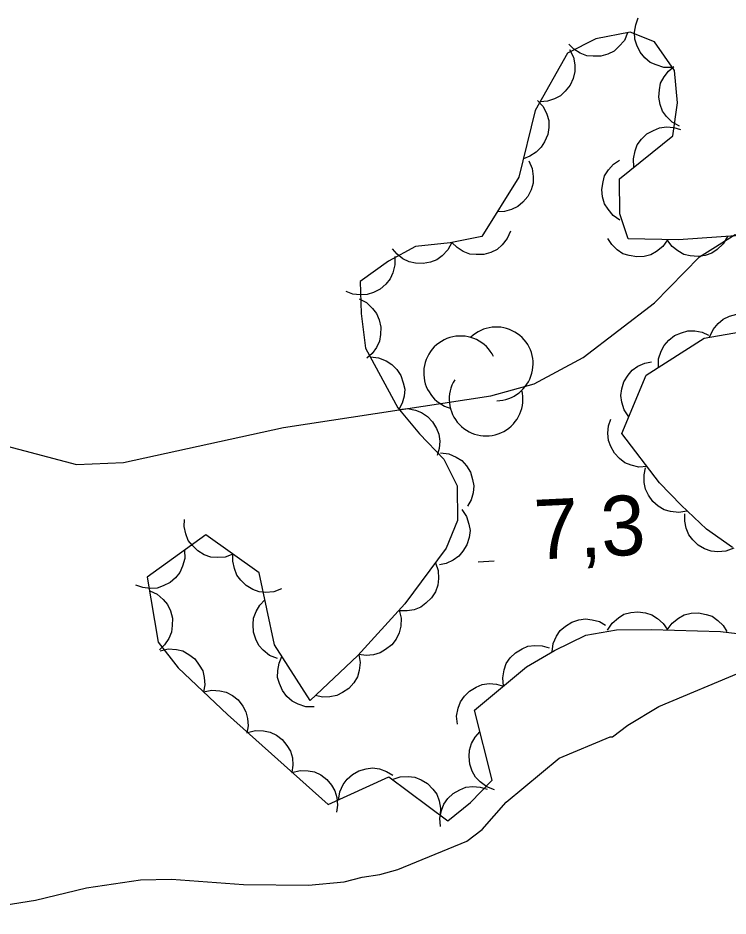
# Model space of a CAD drawing. Extents: x 336540 to 340074, y 5572036 to 5573747.
# Drawn here: x 337087.41 to 337123.07, y 5573176.22 to 5573221.28 of the extents above; entities that cross this region are included whole.
import ezdxf

# ---------------------------------------------------------------- set-up
doc = ezdxf.new("R2010")
doc.units = 0
for name, color, linetype in [('Niveau 2', 7, 'Continuous'), ('Niveau 3', 7, 'Continuous'), ('Niveau 44', 7, 'Continuous')]:
    doc.layers.add(name, color=color, linetype=linetype)

msp = doc.modelspace()

# ---------------------------------------------------------------- linework, layer by layer
at = {"layer": 'Niveau 2'}
for points in [[(337082.81, 5573200.86), (337090.35, 5573198.87), (337092.72, 5573198.98), (337100.75, 5573200.74), (337111.16, 5573202.32), (337113.33, 5573202.93), (337115.79, 5573204.25), (337119.38, 5573206.98), (337121.63, 5573209.29), (337123.43, 5573210.41), (337126.65, 5573210.23), (337131.4, 5573210.47), (337137.08, 5573211.79), (337144.21, 5573214.53), (337147.21, 5573215.37), (337153.27, 5573216.18), (337159.76, 5573218.05)], [(337117.14, 5573185.21), (337117.26, 5573185.21), (337118.03, 5573185.79), (337119.59, 5573186.73), (337123.82, 5573188.51)], [(337083.24, 5573176.22), (337088.29, 5573177.01), (337090.86, 5573177.63), (337093.56, 5573178.03), (337095.13, 5573178.07), (337098.74, 5573177.81), (337102, 5573177.77), (337103.8, 5573177.93), (337104.7, 5573178.17), (337105.59, 5573178.3), (337106.49, 5573178.55), (337109.95, 5573179.98), (337110.72, 5573180.56), (337111.93, 5573181.94), (337114.58, 5573184.14), (337117.14, 5573185.21)]]:
    msp.add_lwpolyline(points, dxfattribs=at)
at = {"layer": 'Niveau 3'}
msp.add_line((337110.52, 5573194), (337111.32, 5573194.04), dxfattribs=at)
at = {"layer": 'Niveau 44'}
for points in [[(337120.26, 5573218.8), (337119.84, 5573218.8), (337119.45, 5573218.92), (337119.15, 5573219.05), (337118.88, 5573219.28), (337118.65, 5573219.57), (337118.48, 5573219.91), (337118.38, 5573220.22), (337118.37, 5573220.57), (337118.43, 5573220.94), (337118.56, 5573221.28)], [(337123.68, 5573210.36), (337120.58, 5573210.14), (337118.05, 5573210.19), (337117.64, 5573211.46), (337117.62, 5573213.21), (337120.29, 5573215.36), (337120.52, 5573217.03), (337120.37, 5573218.64), (337119.38, 5573220.08), (337118.15, 5573220.56), (337116.43, 5573220.23), (337115.01, 5573219.51), (337113.38, 5573216.63), (337112.56, 5573213.3), (337110.7, 5573210.31), (337109.12, 5573210), (337107.37, 5573209.82), (337106.01, 5573209.08), (337104.6, 5573208.06), (337104.64, 5573206.45), (337104.86, 5573204.72), (337106.49, 5573201.72), (337107.57, 5573200.41), (337108.79, 5573199.15), (337109.47, 5573197.81), (337109.48, 5573196.07), (337108.91, 5573194.67), (337106.84, 5573191.88), (337104.48, 5573189.3), (337102.08, 5573187.03), (337100.29, 5573189.83), (337099.52, 5573193.44), (337096.85, 5573195.35), (337093.91, 5573193.23), (337094.46, 5573189.96), (337095.45, 5573188.68), (337097.93, 5573186.33), (337102.99, 5573181.81), (337106.03, 5573183.2), (337108.99, 5573181), (337110.14, 5573181.92), (337111.22, 5573183.04), (337110.34, 5573186.55), (337112.95, 5573188.73), (337114.36, 5573189.54), (337115.93, 5573190.32), (337117.47, 5573190.58), (337119.22, 5573190.6), (337122.69, 5573190.5), (337124.36, 5573190.3)], [(337118.02, 5573220.54), (337117.86, 5573220.15), (337117.59, 5573219.84), (337117.35, 5573219.62), (337117.03, 5573219.47), (337116.68, 5573219.36), (337116.29, 5573219.36), (337115.97, 5573219.38), (337115.64, 5573219.52), (337115.33, 5573219.72), (337115.07, 5573219.97)], [(337115.11, 5573219.69), (337115.3, 5573219.32), (337115.37, 5573218.92), (337115.38, 5573218.59), (337115.29, 5573218.25), (337115.14, 5573217.91), (337114.89, 5573217.61), (337114.66, 5573217.38), (337114.35, 5573217.22), (337114, 5573217.11), (337113.64, 5573217.08)], [(337120.63, 5573215.85), (337120.26, 5573216.05), (337119.98, 5573216.34), (337119.78, 5573216.61), (337119.66, 5573216.94), (337119.59, 5573217.3), (337119.62, 5573217.68), (337119.68, 5573218.01), (337119.85, 5573218.32), (337120.07, 5573218.61), (337120.35, 5573218.84)], [(337113.5, 5573217.14), (337113.78, 5573216.83), (337113.96, 5573216.46), (337114.06, 5573216.14), (337114.06, 5573215.79), (337114.01, 5573215.43), (337113.85, 5573215.07), (337113.69, 5573214.79), (337113.43, 5573214.55), (337113.12, 5573214.35), (337112.79, 5573214.22)], [(337118.34, 5573213.79), (337118.31, 5573214.21), (337118.4, 5573214.61), (337118.51, 5573214.92), (337118.72, 5573215.2), (337118.98, 5573215.46), (337119.32, 5573215.64), (337119.62, 5573215.77), (337119.97, 5573215.81), (337120.34, 5573215.78), (337120.68, 5573215.68)], [(337113.06, 5573214.11), (337113.23, 5573213.73), (337113.28, 5573213.32), (337113.28, 5573212.99), (337113.18, 5573212.66), (337113.01, 5573212.33), (337112.76, 5573212.04), (337112.51, 5573211.82), (337112.19, 5573211.67), (337111.84, 5573211.57), (337111.48, 5573211.56)], [(337117.64, 5573211.14), (337117.29, 5573211.37), (337117.04, 5573211.68), (337116.86, 5573211.96), (337116.77, 5573212.3), (337116.73, 5573212.67), (337116.79, 5573213.05), (337116.87, 5573213.36), (337117.06, 5573213.66), (337117.31, 5573213.94), (337117.61, 5573214.14)], [(337112.14, 5573210.59), (337111.98, 5573210.21), (337111.72, 5573209.9), (337111.48, 5573209.67), (337111.16, 5573209.52), (337110.81, 5573209.42), (337110.42, 5573209.41), (337110.1, 5573209.43), (337109.77, 5573209.57), (337109.46, 5573209.76), (337109.2, 5573210.02)], [(337120.03, 5573210.15), (337119.79, 5573209.81), (337119.47, 5573209.56), (337119.19, 5573209.39), (337118.85, 5573209.31), (337118.48, 5573209.29), (337118.1, 5573209.36), (337117.79, 5573209.45), (337117.5, 5573209.65), (337117.23, 5573209.91), (337117.03, 5573210.21)], [(337123.03, 5573210.31), (337122.82, 5573209.95), (337122.52, 5573209.67), (337122.25, 5573209.48), (337121.92, 5573209.37), (337121.56, 5573209.31), (337121.17, 5573209.35), (337120.85, 5573209.41), (337120.55, 5573209.59), (337120.26, 5573209.82), (337120.04, 5573210.1)], [(337109.2, 5573210.01), (337109, 5573209.64), (337108.72, 5573209.35), (337108.45, 5573209.15), (337108.12, 5573209.03), (337107.76, 5573208.96), (337107.38, 5573208.98), (337107.06, 5573209.04), (337106.74, 5573209.2), (337106.45, 5573209.43), (337106.22, 5573209.7)], [(337106.33, 5573209.31), (337106.34, 5573208.89), (337106.23, 5573208.5), (337106.1, 5573208.19), (337105.88, 5573207.92), (337105.6, 5573207.68), (337105.26, 5573207.51), (337104.95, 5573207.4), (337104.6, 5573207.38), (337104.23, 5573207.43), (337103.89, 5573207.55)], [(337104.55, 5573207.18), (337104.92, 5573207), (337105.21, 5573206.71), (337105.42, 5573206.46), (337105.55, 5573206.13), (337105.63, 5573205.77), (337105.61, 5573205.39), (337105.57, 5573205.06), (337105.41, 5573204.75), (337105.2, 5573204.45), (337104.93, 5573204.21)], [(337122.13, 5573205.27), (337122.31, 5573205.65), (337122.57, 5573205.95), (337122.82, 5573206.17), (337123.14, 5573206.32), (337123.5, 5573206.41), (337123.88, 5573206.41), (337124.21, 5573206.38), (337124.53, 5573206.24), (337124.84, 5573206.03), (337125.09, 5573205.77)], [(337123.29, 5573194.71), (337121.99, 5573195.63), (337120.71, 5573196.83), (337119.63, 5573197.96), (337117.73, 5573200.43), (337118.95, 5573203.36), (337121.86, 5573205.22), (337125.13, 5573205.78)], [(337119.57, 5573203.75), (337119.58, 5573204.17), (337119.7, 5573204.56), (337119.85, 5573204.85), (337120.09, 5573205.11), (337120.38, 5573205.34), (337120.73, 5573205.49), (337121.05, 5573205.58), (337121.4, 5573205.58), (337121.76, 5573205.51), (337122.09, 5573205.37)], [(337105.11, 5573204.27), (337105.52, 5573204.23), (337105.9, 5573204.07), (337106.18, 5573203.9), (337106.43, 5573203.65), (337106.63, 5573203.34), (337106.75, 5573202.98), (337106.83, 5573202.66), (337106.8, 5573202.31), (337106.7, 5573201.95), (337106.54, 5573201.63)], [(337118.08, 5573201.26), (337117.85, 5573201.61), (337117.73, 5573202), (337117.68, 5573202.33), (337117.73, 5573202.68), (337117.84, 5573203.03), (337118.05, 5573203.36), (337118.25, 5573203.61), (337118.54, 5573203.81), (337118.88, 5573203.96), (337119.23, 5573204.03)], [(337106.55, 5573201.64), (337106.97, 5573201.68), (337107.37, 5573201.6), (337107.68, 5573201.49), (337107.97, 5573201.29), (337108.23, 5573201.02), (337108.42, 5573200.69), (337108.55, 5573200.39), (337108.59, 5573200.04), (337108.56, 5573199.67), (337108.46, 5573199.33)], [(337119.01, 5573198.77), (337118.59, 5573198.74), (337118.2, 5573198.84), (337117.89, 5573198.96), (337117.61, 5573199.17), (337117.36, 5573199.44), (337117.18, 5573199.78), (337117.06, 5573200.08), (337117.03, 5573200.44), (337117.07, 5573200.81), (337117.18, 5573201.15)], [(337108.63, 5573199.46), (337109.05, 5573199.41), (337109.42, 5573199.24), (337109.7, 5573199.07), (337109.93, 5573198.81), (337110.13, 5573198.49), (337110.24, 5573198.13), (337110.31, 5573197.81), (337110.27, 5573197.46), (337110.16, 5573197.1), (337109.99, 5573196.79)], [(337121, 5573196.53), (337120.59, 5573196.46), (337120.18, 5573196.51), (337119.86, 5573196.6), (337119.56, 5573196.78), (337119.29, 5573197.02), (337119.07, 5573197.34), (337118.92, 5573197.63), (337118.85, 5573197.98), (337118.85, 5573198.35), (337118.92, 5573198.7)], [(337109.7, 5573196.62), (337109.94, 5573196.27), (337110.05, 5573195.88), (337110.11, 5573195.56), (337110.06, 5573195.21), (337109.95, 5573194.85), (337109.75, 5573194.53), (337109.55, 5573194.27), (337109.26, 5573194.07), (337108.92, 5573193.91), (337108.57, 5573193.84)], [(337098.21, 5573194.38), (337097.82, 5573194.23), (337097.41, 5573194.21), (337097.09, 5573194.23), (337096.76, 5573194.35), (337096.44, 5573194.54), (337096.17, 5573194.81), (337095.96, 5573195.07), (337095.84, 5573195.4), (337095.76, 5573195.76), (337095.77, 5573196.12)], [(337123.35, 5573194.67), (337122.96, 5573194.52), (337122.55, 5573194.5), (337122.22, 5573194.52), (337121.89, 5573194.64), (337121.57, 5573194.83), (337121.3, 5573195.1), (337121.09, 5573195.35), (337120.97, 5573195.68), (337120.89, 5573196.04), (337120.9, 5573196.4)], [(337095.78, 5573194.58), (337095.79, 5573194.16), (337095.68, 5573193.77), (337095.55, 5573193.46), (337095.33, 5573193.19), (337095.05, 5573192.95), (337094.71, 5573192.78), (337094.4, 5573192.67), (337094.05, 5573192.65), (337093.68, 5573192.7), (337093.34, 5573192.82)], [(337100.65, 5573192.63), (337100.26, 5573192.48), (337099.85, 5573192.46), (337099.53, 5573192.48), (337099.2, 5573192.61), (337098.88, 5573192.8), (337098.61, 5573193.07), (337098.4, 5573193.32), (337098.28, 5573193.65), (337098.2, 5573194.02), (337098.21, 5573194.38)], [(337108.38, 5573193.95), (337108.51, 5573193.56), (337108.53, 5573193.15), (337108.5, 5573192.82), (337108.37, 5573192.49), (337108.18, 5573192.18), (337107.9, 5573191.91), (337107.64, 5573191.71), (337107.31, 5573191.59), (337106.95, 5573191.53), (337106.59, 5573191.54)], [(337094.03, 5573192.54), (337094.41, 5573192.37), (337094.71, 5573192.1), (337094.93, 5573191.85), (337095.07, 5573191.53), (337095.17, 5573191.17), (337095.16, 5573190.79), (337095.13, 5573190.46), (337094.99, 5573190.14), (337094.78, 5573189.83), (337094.52, 5573189.58)], [(337100.44, 5573189.14), (337100.05, 5573189.3), (337099.73, 5573189.56), (337099.51, 5573189.8), (337099.35, 5573190.11), (337099.24, 5573190.46), (337099.22, 5573190.85), (337099.24, 5573191.17), (337099.37, 5573191.5), (337099.56, 5573191.82), (337099.81, 5573192.08)], [(337106.56, 5573191.57), (337106.65, 5573191.16), (337106.63, 5573190.76), (337106.56, 5573190.43), (337106.4, 5573190.12), (337106.18, 5573189.83), (337105.87, 5573189.59), (337105.6, 5573189.42), (337105.26, 5573189.33), (337104.89, 5573189.3), (337104.53, 5573189.35)], [(337114.23, 5573189.48), (337114.29, 5573189.89), (337114.46, 5573190.26), (337114.64, 5573190.54), (337114.9, 5573190.77), (337115.22, 5573190.97), (337115.58, 5573191.08), (337115.9, 5573191.14), (337116.25, 5573191.09), (337116.61, 5573190.99), (337116.92, 5573190.81)], [(337117.02, 5573190.57), (337117.25, 5573190.92), (337117.56, 5573191.18), (337117.84, 5573191.36), (337118.18, 5573191.45), (337118.54, 5573191.49), (337118.92, 5573191.43), (337119.24, 5573191.34), (337119.53, 5573191.15), (337119.81, 5573190.9), (337120.01, 5573190.61)], [(337120.01, 5573190.58), (337120.26, 5573190.92), (337120.58, 5573191.16), (337120.87, 5573191.33), (337121.21, 5573191.41), (337121.58, 5573191.43), (337121.96, 5573191.35), (337122.27, 5573191.26), (337122.56, 5573191.05), (337122.82, 5573190.79), (337123.01, 5573190.49)], [(337111.79, 5573187.76), (337111.75, 5573188.18), (337111.82, 5573188.57), (337111.93, 5573188.89), (337112.13, 5573189.17), (337112.4, 5573189.43), (337112.73, 5573189.63), (337113.02, 5573189.76), (337113.37, 5573189.8), (337113.74, 5573189.78), (337114.09, 5573189.68)], [(337094.55, 5573189.53), (337094.96, 5573189.62), (337095.37, 5573189.59), (337095.69, 5573189.52), (337096, 5573189.35), (337096.29, 5573189.12), (337096.52, 5573188.81), (337096.69, 5573188.53), (337096.77, 5573188.19), (337096.79, 5573187.82), (337096.73, 5573187.47)], [(337104.53, 5573189.35), (337104.6, 5573188.94), (337104.55, 5573188.54), (337104.46, 5573188.22), (337104.28, 5573187.92), (337104.03, 5573187.64), (337103.71, 5573187.43), (337103.42, 5573187.28), (337103.08, 5573187.22), (337102.71, 5573187.21), (337102.35, 5573187.29)], [(337102.28, 5573186.71), (337101.87, 5573186.72), (337101.48, 5573186.85), (337101.18, 5573187), (337100.92, 5573187.23), (337100.7, 5573187.53), (337100.55, 5573187.88), (337100.45, 5573188.19), (337100.46, 5573188.54), (337100.53, 5573188.91), (337100.67, 5573189.24)], [(337096.73, 5573187.47), (337097.14, 5573187.56), (337097.55, 5573187.52), (337097.87, 5573187.45), (337098.18, 5573187.29), (337098.47, 5573187.06), (337098.7, 5573186.75), (337098.86, 5573186.47), (337098.94, 5573186.13), (337098.97, 5573185.76), (337098.91, 5573185.4)], [(337109.49, 5573185.84), (337109.44, 5573186.25), (337109.52, 5573186.65), (337109.63, 5573186.96), (337109.83, 5573187.25), (337110.09, 5573187.51), (337110.42, 5573187.7), (337110.72, 5573187.84), (337111.07, 5573187.88), (337111.44, 5573187.86), (337111.79, 5573187.76)], [(337098.94, 5573185.43), (337099.34, 5573185.53), (337099.75, 5573185.51), (337100.07, 5573185.45), (337100.39, 5573185.29), (337100.68, 5573185.07), (337100.92, 5573184.77), (337101.1, 5573184.5), (337101.19, 5573184.16), (337101.22, 5573183.79), (337101.17, 5573183.43)], [(337111.34, 5573182.56), (337110.95, 5573182.7), (337110.62, 5573182.95), (337110.39, 5573183.18), (337110.22, 5573183.49), (337110.1, 5573183.84), (337110.07, 5573184.22), (337110.08, 5573184.54), (337110.19, 5573184.88), (337110.37, 5573185.2), (337110.61, 5573185.47)], [(337101.17, 5573183.43), (337101.58, 5573183.53), (337101.98, 5573183.51), (337102.31, 5573183.46), (337102.62, 5573183.3), (337102.92, 5573183.07), (337103.16, 5573182.78), (337103.33, 5573182.5), (337103.42, 5573182.16), (337103.46, 5573181.79), (337103.41, 5573181.43)], [(337103.5, 5573182.04), (337103.57, 5573182.46), (337103.75, 5573182.82), (337103.94, 5573183.09), (337104.21, 5573183.32), (337104.53, 5573183.5), (337104.9, 5573183.6), (337105.22, 5573183.65), (337105.57, 5573183.6), (337105.92, 5573183.48), (337106.23, 5573183.29)], [(337106.21, 5573183.07), (337106.6, 5573183.21), (337107.01, 5573183.22), (337107.34, 5573183.19), (337107.66, 5573183.06), (337107.98, 5573182.87), (337108.24, 5573182.59), (337108.44, 5573182.33), (337108.56, 5573182), (337108.63, 5573181.64), (337108.62, 5573181.28)], [(337108.63, 5573180.71), (337108.59, 5573181.13), (337108.68, 5573181.52), (337108.79, 5573181.83), (337109, 5573182.12), (337109.27, 5573182.37), (337109.6, 5573182.56), (337109.9, 5573182.68), (337110.25, 5573182.72), (337110.62, 5573182.69), (337110.97, 5573182.58)]]:
    msp.add_lwpolyline(points, dxfattribs=at)
for centre, start, end in [((337111.428, 5573203.924), 271.0121, 133.6965), ((337109.634, 5573203.474), 26.3444, 253.8015), ((337110.918, 5573202.156), 148.1906, 13.8792)]:
    msp.add_arc(centre, 1.85, start, end, dxfattribs=at)

# ---------------------------------------------------------------- texts
at = {"layer": 'Niveau 3'}
msp.add_text('7,3    ', height=3, rotation=2.7712, dxfattribs=at).set_placement((337113.4, 5573194.1))

doc.saveas('drawing.dxf')
